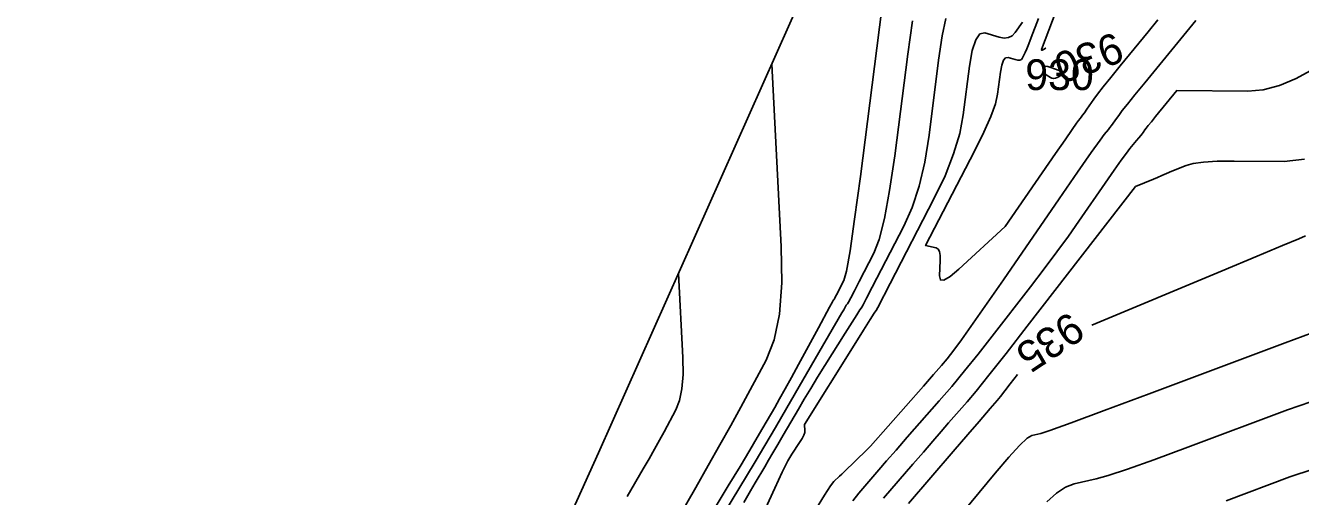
# Model space of a CAD drawing. Extents: x 2175772 to 2185556, y 721391 to 722853.
# Drawn here: x 2178632.3 to 2178748.5, y 722055.4 to 722098.3 of the extents above; entities that cross this region are included whole.
import ezdxf

# ---------------------------------------------------------------- set-up
doc = ezdxf.new("R2010")
doc.units = 0
for name, color, linetype in [('DT_X_Contour_Major', 7, 'Continuous'), ('DT_X_Contour_Minor', 7, 'Continuous'), ('DT_X_TIN_Hull', 7, 'Continuous')]:
    doc.layers.add(name, color=color, linetype=linetype)

msp = doc.modelspace()

# ---------------------------------------------------------------- linework, layer by layer
at = {"layer": 'DT_X_Contour_Major'}
for points in [[(2178727.16, 722102.1), (2178724.91, 722096.14), (2178724.95, 722096.07), (2178724.98, 722096.08), (2178725.04, 722096.11), (2178725.14, 722096.19), (2178725.27, 722096.29), (2178725.29, 722096.32)], [(2178710.39, 722100.1), (2178709.9, 722096.27), (2178708.39, 722084.59), (2178707.87, 722080.71), (2178707.45, 722077.83), (2178707.12, 722075.97), (2178706.89, 722075.1), (2178706.22, 722073.82), (2178706.1, 722073.59), (2178706.02, 722073.45), (2178705.99, 722073.39), (2178705.95, 722073.34), (2178705.85, 722073.17), (2178705.59, 722072.68), (2178704.56, 722070.8), (2178702.76, 722067.46), (2178702.11, 722066.28), (2178701.54, 722065.24), (2178701.03, 722064.33), (2178700.58, 722063.55), (2178699.49, 722061.68), (2178698.99, 722060.82), (2178698.3, 722059.65), (2178697.42, 722058.18), (2178696.35, 722056.4), (2178693.24, 722051.25)], [(2178726.78, 722093.86), (2178726.89, 722093.95), (2178726.89, 722094.05), (2178726.77, 722094.15), (2178726.53, 722094.25), (2178725.75, 722094.52), (2178725.49, 722094.6), (2178725.3, 722094.63), (2178725.18, 722094.6), (2178725.13, 722094.52), (2178725.09, 722094.25), (2178725.1, 722094.15), (2178725.14, 722094.05), (2178725.22, 722093.95), (2178725.34, 722093.86), (2178725.72, 722093.61), (2178725.86, 722093.54), (2178726.01, 722093.51), (2178726.17, 722093.54), (2178726.33, 722093.61), (2178726.78, 722093.86)], [(2178729.5, 722071.03), (2178741.39, 722076), (2178744.56, 722077.33), (2178746.88, 722078.3), (2178748.36, 722078.91), (2178748.98, 722079.17)], [(2178712.78, 722054.8), (2178716.84, 722059.53), (2178718.2, 722061.1), (2178719.21, 722062.28), (2178719.88, 722063.06), (2178720.22, 722063.44), (2178720.65, 722063.94), (2178720.86, 722064.19), (2178721.17, 722064.56), (2178721.57, 722065.07), (2178722.06, 722065.71), (2178722.71, 722066.54)]]:
    msp.add_lwpolyline(points, dxfattribs=at)
at = {"layer": 'DT_X_Contour_Minor'}
for points in [[(2178713.13, 722098.76), (2178712.71, 722095.72), (2178711.52, 722086.46), (2178711.06, 722083.3), (2178710.6, 722080.77), (2178710.12, 722078.86), (2178709.62, 722077.59), (2178708.29, 722075.01), (2178707.85, 722074.16), (2178707.52, 722073.54), (2178707.31, 722073.15), (2178707.21, 722072.99), (2178707.11, 722072.86), (2178707.07, 722072.81), (2178707.03, 722072.75), (2178707, 722072.69), (2178706.96, 722072.63), (2178706.87, 722072.45), (2178706.7, 722072.16), (2178704.61, 722068.55), (2178701.69, 722063.52), (2178700.64, 722061.72), (2178699.68, 722060.08), (2178698.8, 722058.6), (2178698.01, 722057.28), (2178696.01, 722053.97)], [(2178716.19, 722098.97), (2178715.86, 722097.41), (2178715.53, 722095.18), (2178714.65, 722088.34), (2178714.26, 722085.9), (2178713.75, 722083.71), (2178713.11, 722081.76), (2178712.36, 722080.07), (2178709.48, 722074.5), (2178708.96, 722073.51), (2178708.64, 722072.9), (2178708.52, 722072.68), (2178708.45, 722072.59), (2178708.34, 722072.43), (2178708.06, 722071.99), (2178707.01, 722070.32), (2178705.16, 722067.38), (2178704.49, 722066.3), (2178703.86, 722065.28), (2178703.28, 722064.31), (2178702.74, 722063.39), (2178701.36, 722061.02), (2178700.87, 722060.17), (2178700.42, 722059.41), (2178700.02, 722058.74), (2178699.67, 722058.15), (2178698.79, 722056.69), (2178698.37, 722055.97), (2178697.78, 722054.9)], [(2178723.18, 722098.64), (2178722.51, 722097.7), (2178722.23, 722097.41), (2178721.89, 722097.24), (2178721.49, 722097.19), (2178721.04, 722097.27), (2178719.74, 722097.66), (2178719.29, 722097.57), (2178718.91, 722097.04), (2178718.59, 722096.06), (2178718.35, 722094.63), (2178717.78, 722090.21), (2178717.45, 722088.49), (2178716.89, 722086.64), (2178716.11, 722084.66), (2178715.1, 722082.55), (2178711.11, 722074.85), (2178709.97, 722072.66), (2178709.82, 722072.38), (2178709.79, 722072.34), (2178709.66, 722072.14), (2178709.29, 722071.55), (2178708.68, 722070.58), (2178707.83, 722069.22), (2178703.29, 722062), (2178703.34, 722061.42), (2178703.32, 722061.26), (2178703.23, 722061.03), (2178703.07, 722060.73), (2178702.84, 722060.36), (2178702.13, 722059.29), (2178701.78, 722058.68), (2178701.27, 722057.65), (2178700.59, 722056.2), (2178699.75, 722054.34)], [(2178704.31, 722054.23), (2178705.11, 722055.55), (2178705.67, 722056.41), (2178705.98, 722056.81), (2178706.48, 722057.28), (2178706.69, 722057.47), (2178706.95, 722057.72), (2178707.25, 722058.01), (2178707.6, 722058.34), (2178709.33, 722060.02), (2178714.14, 722065.49), (2178715.06, 722066.55), (2178715.79, 722067.38), (2178716.31, 722067.99), (2178716.62, 722068.38), (2178717.19, 722069.12), (2178717.62, 722069.7), (2178718.47, 722070.91), (2178719.74, 722072.74), (2178721.43, 722075.18), (2178726.52, 722082.54), (2178728.2, 722084.98), (2178729.45, 722086.77), (2178730.25, 722087.91), (2178730.62, 722088.41), (2178731.01, 722088.87), (2178731.15, 722089.05), (2178731.3, 722089.24), (2178731.45, 722089.44), (2178731.61, 722089.66), (2178732.01, 722090.24), (2178732.27, 722090.59), (2178732.74, 722091.18), (2178733.42, 722092.02), (2178734.32, 722093.11), (2178738.97, 722098.79)], [(2178724.62, 722098.99), (2178723.96, 722097.25), (2178723.74, 722096.66), (2178723.56, 722096.21), (2178723.42, 722095.88), (2178723.33, 722095.69), (2178723.16, 722095.34), (2178723.07, 722095.24), (2178722.93, 722095.19), (2178722.75, 722095.18), (2178722.52, 722095.23), (2178721.86, 722095.43), (2178721.63, 722095.4), (2178721.43, 722095.17), (2178721.28, 722094.73), (2178721.16, 722094.08), (2178720.91, 722092.09), (2178720.7, 722091.2), (2178720.28, 722090.04), (2178719.65, 722088.61), (2178718.8, 722086.9), (2178714.34, 722078.29), (2178715.31, 722078.08), (2178715.49, 722077.98), (2178715.61, 722077.75), (2178715.67, 722077.4), (2178715.67, 722076.93), (2178715.6, 722075.53), (2178715.69, 722075.17), (2178716.01, 722075.15), (2178716.57, 722075.47), (2178717.36, 722076.14), (2178721.58, 722080.03), (2178726.18, 722086.68), (2178727.06, 722087.94), (2178727.69, 722088.86), (2178728.1, 722089.44), (2178728.28, 722089.68), (2178728.44, 722089.88), (2178728.52, 722089.98), (2178728.65, 722090.16), (2178728.83, 722090.4), (2178729.05, 722090.71), (2178729.69, 722091.64), (2178730.02, 722092.09), (2178730.53, 722092.74), (2178731.22, 722093.6), (2178732.09, 722094.67), (2178734.64, 722097.77), (2178735.53, 722098.86)], [(2178700.31, 722094.83), (2178701.17, 722078.21), (2178701.23, 722074.89), (2178701.02, 722072.06), (2178700.54, 722069.72), (2178699.81, 722067.87), (2178697.48, 722063.58), (2178696.57, 722061.92), (2178695.59, 722060.14), (2178694.52, 722058.25), (2178693.38, 722056.25), (2178690.22, 722050.77)], [(2178707.71, 722055.06), (2178708.25, 722055.75), (2178709.52, 722057.23), (2178710.07, 722057.87), (2178710.78, 722058.68), (2178711.65, 722059.67), (2178712.67, 722060.83), (2178715.59, 722064.16), (2178716.72, 722065.46), (2178717.89, 722066.88), (2178719.12, 722068.4), (2178720.4, 722070.03), (2178723.89, 722074.53), (2178725.15, 722076.17), (2178726.3, 722077.71), (2178727.36, 722079.16), (2178728.31, 722080.51), (2178730.7, 722083.98), (2178731.52, 722085.15), (2178732.17, 722086.06), (2178732.65, 722086.72), (2178732.96, 722087.13), (2178733.58, 722087.86), (2178733.79, 722088.12), (2178733.96, 722088.32), (2178734.08, 722088.48), (2178734.17, 722088.6), (2178734.34, 722088.84), (2178734.45, 722088.99), (2178734.64, 722089.23), (2178734.93, 722089.58), (2178735.3, 722090.04), (2178737.24, 722092.41), (2178743.71, 722092.37), (2178745.12, 722092.49), (2178746.6, 722092.86), (2178748.14, 722093.5), (2178749.74, 722094.38)], [(2178710.51, 722055.28), (2178713.18, 722058.38), (2178714.14, 722059.49), (2178715, 722060.48), (2178715.77, 722061.36), (2178716.44, 722062.14), (2178718.12, 722064.05), (2178718.94, 722065.02), (2178720.12, 722066.49), (2178721.68, 722068.46), (2178723.61, 722070.94), (2178733.48, 722083.67), (2178735.12, 722084.35), (2178735.48, 722084.51), (2178735.89, 722084.68), (2178736.32, 722084.86), (2178736.79, 722085.06), (2178738.1, 722085.6), (2178738.74, 722085.78), (2178739.68, 722085.9), (2178740.94, 722085.97), (2178742.49, 722085.99), (2178747.05, 722085.96), (2178748.88, 722086.16)], [(2178691.8, 722075.76), (2178692.2, 722068.09), (2178692.22, 722066.56), (2178692.12, 722065.25), (2178691.9, 722064.17), (2178691.56, 722063.32), (2178690.49, 722061.34), (2178690.07, 722060.57), (2178689.62, 722059.75), (2178689.12, 722058.88), (2178688.6, 722057.96), (2178687.14, 722055.43)], [(2178717.03, 722053.15), (2178720.69, 722057.56), (2178721.93, 722059.02), (2178722.9, 722060.08), (2178723.61, 722060.74), (2178724.04, 722061.01), (2178724.84, 722061.19), (2178725.68, 722061.46), (2178727.61, 722062.16), (2178730.62, 722063.27), (2178734.73, 722064.8), (2178747.12, 722069.44), (2178751.24, 722070.95)], [(2178725.38, 722054.96), (2178726.27, 722055.75), (2178727.1, 722056.29), (2178727.89, 722056.59), (2178729.9, 722057.04), (2178730.99, 722057.35), (2178732.74, 722057.93), (2178735.16, 722058.79), (2178738.24, 722059.93), (2178747.33, 722063.33), (2178750.53, 722064.42)], [(2178741.75, 722055.06), (2178747.55, 722057.23), (2178749.69, 722057.92)]]:
    msp.add_lwpolyline(points, dxfattribs=at)
at = {"layer": 'DT_X_TIN_Hull'}
msp.add_lwpolyline([(2178706.95, 722109.71), (2178684.5, 722059.42), (2178647.66, 721977.89), (2178647.62, 721976.89), (2178647.56, 721975.92), (2178646.89, 721975.04), (2178647.05, 721974.53), (2178646.26, 721973.92), (2178645.27, 721973), (2178625.76, 721928.99)], dxfattribs=at)

# ---------------------------------------------------------------- texts
at = {"layer": 'DT_X_Contour_Major'}
for s, rotation, p in [('930', 200.4392, (2178731.66, 722097.8)), ('935', 213.4911, (2178727.54, 722072.37))]:
    msp.add_text(s, height=2.8, rotation=rotation, dxfattribs=at).set_placement(p)
msp.add_text('930', height=2.8, dxfattribs=at).set_placement((2178723.43, 722092.46))

doc.saveas('drawing.dxf')
